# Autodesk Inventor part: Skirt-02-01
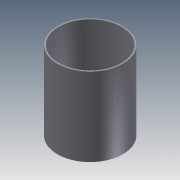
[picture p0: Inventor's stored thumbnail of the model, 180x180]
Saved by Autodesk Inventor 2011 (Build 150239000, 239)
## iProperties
Created: 2010-06
Part Number: Skirt-02-01
Document SubType Name: Modeling
Designer: mklassen
Density: 1 g/cm^3
OD: 24.000 in
THK: 0.500 in
LEN: 2.500 ft
SKVOFS: 6.000 in
Author: mklassen
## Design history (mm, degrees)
sketch "skSkirt"
  geometry: C1 r 317.5 at (0, 0); C2 r 304.8 at (0, 0); 1 further point
  constraints: 2 centre point, 1 coincident
  dimensions: "d0" = 609.6 diameter of C2 (derived); "d1" = 12.7 radial gap between concentric circles of C1 C2 (derived)
extrude "Extrusion1" new body sketch "skSkirt" stored distance "d2" = 762 (derived); taper "d3" = 0 deg
body "Solid1"
other parameters: "d4" = 152.4 (derived), "d5" = 0
